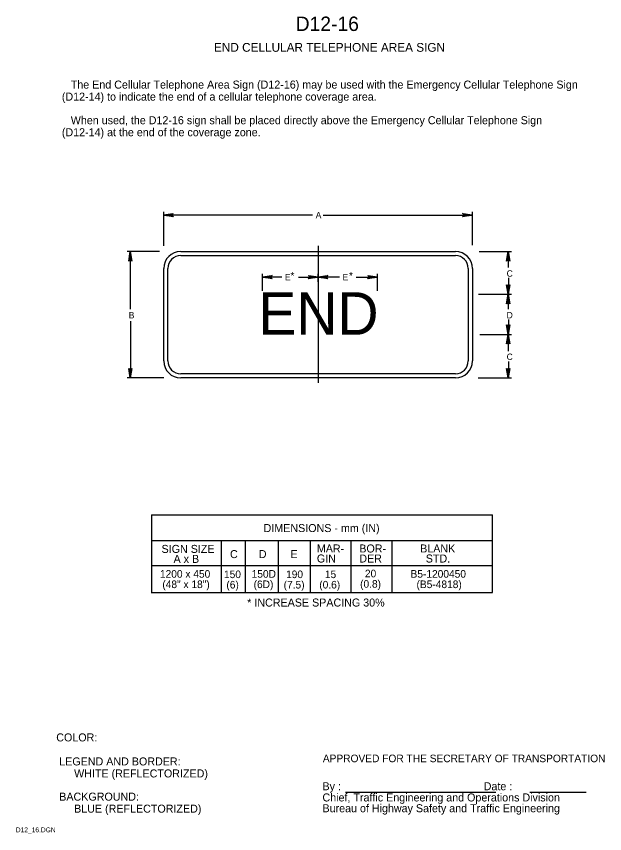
# Model space of a CAD drawing. Extents: x 0.013 to 0.196, y 0.004 to 0.259.
import ezdxf

# ---------------------------------------------------------------- set-up
doc = ezdxf.new("R2010")
doc.units = 0
for name, color, linetype in [('Level 1', 7, 'Continuous'), ('Level 2', 7, 'Continuous'), ('Level 3', 7, 'Continuous')]:
    doc.layers.add(name, color=color, linetype=linetype)

# ---------------------------------------------------------------- blocks, each defined once
blk = doc.blocks.new('RARROW')
at = {"layer": 'Level 3'}
for p, q in [((-2.156, 0.285), (-2.2665, 0.384625)), ((-2.2665, 0.384625), (0, 0)), ((0, 0), (-2.2665, -0.379125)), ((-2.156, 0.285), (-2.075625, 0.12075)), ((0, 0), (-2.156, 0.285)), ((-2.14975, -0.2705), (0, 0)), ((-2.075625, 0.12075), (0, 0)), ((0, 0), (-2.074, -0.108)), ((-2.2665, -0.379125), (-2.14975, -0.2705)), ((-2.074, -0.108), (-2.14975, -0.2705))]:
    blk.add_line(p, q, dxfattribs=at)

msp = doc.modelspace()

# ---------------------------------------------------------------- linework, layer by layer
at = {"layer": 'Level 1'}
for p, q in [((0.10687, 0.1875), (0.10687, 0.14475)), ((0.11544, 0.01695), (0.16242, 0.01695)), ((0.17295, 0.01695), (0.19056, 0.01695))]:
    msp.add_line(p, q, dxfattribs=at)
at = {"layer": 'Level 3'}
for p, q in [((0.05868, 0.18751), (0.05868, 0.19813)), ((0.10518, 0.19713), (0.05868, 0.19713)), ((0.10843, 0.19713), (0.15506, 0.19713)), ((0.15506, 0.18776), (0.15506, 0.19813)), ((0.05731, 0.18576), (0.04731, 0.18576)), ((0.04831, 0.16776), (0.04831, 0.18576)), ((0.06398, 0.18576), (0.14976, 0.18576)), ((0.06398, 0.18446), (0.14976, 0.18446)), ((0.15718, 0.18576), (0.16731, 0.18576)), ((0.16631, 0.18076), (0.16631, 0.18576)), ((0.05868, 0.15156), (0.05868, 0.18046)), ((0.05998, 0.15156), (0.05998, 0.18046)), ((0.08956, 0.17345), (0.08956, 0.17876)), ((0.10693, 0.17626), (0.10693, 0.17876)), ((0.12543, 0.17345), (0.12543, 0.17876)), ((0.15376, 0.18046), (0.15376, 0.15156)), ((0.15506, 0.18046), (0.15506, 0.15156)), ((0.09556, 0.17776), (0.08956, 0.17776)), ((0.10081, 0.17776), (0.10693, 0.17776)), ((0.11356, 0.17776), (0.10693, 0.17776)), ((0.11881, 0.17776), (0.12543, 0.17776)), ((0.16631, 0.17751), (0.16631, 0.17238)), ((0.15693, 0.17238), (0.16731, 0.17238)), ((0.16631, 0.16776), (0.16631, 0.17238)), ((0.04831, 0.16401), (0.04831, 0.14626)), ((0.16631, 0.16451), (0.16631, 0.15988)), ((0.15743, 0.15988), (0.16731, 0.15988)), ((0.16631, 0.15463), (0.16631, 0.15988)), ((0.16631, 0.15138), (0.16631, 0.14626)), ((0.05868, 0.14626), (0.04731, 0.14626)), ((0.14976, 0.14756), (0.06398, 0.14756)), ((0.14976, 0.14626), (0.06398, 0.14626)), ((0.15681, 0.14626), (0.16731, 0.14626)), ((0.05489, 0.10349), (0.05489, 0.07926)), ((0.05491, 0.10351), (0.16133, 0.10351)), ((0.16125, 0.1035), (0.16125, 0.07925)), ((0.16133, 0.09539), (0.055, 0.09539)), ((0.07664, 0.09524), (0.07664, 0.07926)), ((0.08414, 0.09549), (0.08414, 0.07926)), ((0.09439, 0.09524), (0.09439, 0.07926)), ((0.10439, 0.09524), (0.10439, 0.07926)), ((0.11714, 0.09524), (0.11714, 0.07926)), ((0.12989, 0.09524), (0.12989, 0.07926)), ((0.05471, 0.08764), (0.16133, 0.08764)), ((0.05471, 0.07926), (0.16133, 0.07926))]:
    msp.add_line(p, q, dxfattribs=at)
for centre, radius, start, end in [((0.06398, 0.18046), 0.0053, 90, 180), ((0.06398, 0.18046), 0.004, 90, 180), ((0.14976, 0.18046), 0.0053, 0, 90), ((0.14976, 0.18046), 0.004, 0, 90), ((0.06398, 0.15156), 0.0053, 180, 270), ((0.06398, 0.15156), 0.004, 180, 270), ((0.14976, 0.15156), 0.0053, 270, 0), ((0.14976, 0.15156), 0.004, 270, 0)]:
    msp.add_arc(centre, radius, start, end, dxfattribs=at)

# ---------------------------------------------------------------- block references
at = {"layer": 'Level 3', "xscale": 0.0013236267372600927, "yscale": 0.001309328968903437}
for p, rotation in [((0.05863, 0.19712), 180), ((0.04825, 0.18575), 90), ((0.16625, 0.18575), 90), ((0.0895, 0.17775), 180), ((0.10687, 0.17775), 180), ((0.16625, 0.17238), -90), ((0.16625, 0.17238), 90), ((0.16625, 0.15988), -90), ((0.16625, 0.15988), 90), ((0.04825, 0.14625), -90), ((0.16625, 0.14625), -90)]:
    msp.add_blockref('RARROW', p, dxfattribs=dict(at, rotation=rotation))
for p in [(0.155, 0.19712), (0.10687, 0.17775), (0.12538, 0.17775)]:
    msp.add_blockref('RARROW', p, dxfattribs=at)

# ---------------------------------------------------------------- texts
at = {"layer": 'Level 1'}
for s, height, p in [('D12-16', 0.0045, (0.09988, 0.25462)), ('END CELLULAR TELEPHONE AREA SIGN', 0.0027503, (0.07437, 0.24813)), ('COLOR:', 0.0025, (0.02513, 0.03275)), ('APPROVED FOR THE SECRETARY OF TRANSPORTATION', 0.0023752, (0.10837, 0.02625)), (' LEGEND AND BORDER:', 0.0024998, (0.02513, 0.02525)), ('      WHITE (REFLECTORIZED)', 0.0024998, (0.02513, 0.0215)), ('By :                                                Date :', 0.0024998, (0.10825, 0.0175)), (' BACKGROUND:', 0.0024998, (0.02513, 0.01425)), ('Chief, Traffic Engineering and Operations Division', 0.0024998, (0.10825, 0.014)), ('      BLUE (REFLECTORIZED)', 0.0024998, (0.02513, 0.0105)), ('Bureau of Highway Safety and Traffic Engineering', 0.0024998, (0.10825, 0.01063)), ('D12_16.DGN', 0.0015, (0.0125, 0.00438))]:
    msp.add_text(s, height=height, dxfattribs=at).set_placement(p)
at = {"layer": 'Level 2'}
for s, height, p in [('   The End Cellular Telephone Area Sign (D12-16) may be used with the Emergency Cellular Telephone Sign', 0.00249975, (0.02687, 0.23663)), ('(D12-14) to indicate the end of a cellular telephone coverage area.', 0.0024998, (0.02687, 0.23287)), ('   When used, the D12-16 sign shall be placed directly above the Emergency Cellular Telephone Sign', 0.0024998, (0.02687, 0.2255)), ('(D12-14) at the end of the coverage zone.', 0.0024998, (0.02687, 0.22175))]:
    msp.add_text(s, height=height, dxfattribs=at).set_placement(p)
at = {"layer": 'Level 3'}
for s, height, p in [('A', 0.002, (0.10612, 0.19612)), ('E ', 0.002, (0.0965, 0.17675)), ('*', 0.00238, (0.09825, 0.177)), ('E ', 0.002, (0.1145, 0.17675)), ('*', 0.00238, (0.1165, 0.177)), ('C', 0.002, (0.16575, 0.17788)), ('END', 0.013289, (0.08825, 0.15975)), ('B', 0.002, (0.04775, 0.16487)), ('D', 0.002, (0.16575, 0.16487)), ('C', 0.002, (0.16575, 0.15188)), ('DIMENSIONS - mm (IN)', 0.0024998, (0.08987, 0.09813)), ('SIGN SIZE', 0.0025, (0.058, 0.09162)), ('C', 0.0025, (0.07938, 0.09)), ('D', 0.0025, (0.08837, 0.09)), ('E', 0.0025, (0.09825, 0.09)), ('MAR-', 0.0025, (0.1065, 0.09175)), ('BOR-', 0.0025, (0.11975, 0.09175)), ('BLANK', 0.0025, (0.13875, 0.09175)), ('A x B', 0.0025, (0.06175, 0.0885)), ('GIN', 0.0025, (0.1065, 0.08862)), ('DER', 0.0025, (0.11975, 0.08862)), ('STD.', 0.0025, (0.1405, 0.08862)), ('1200 x 450', 0.002375, (0.0575, 0.08388)), ('150', 0.002375, (0.0775, 0.08375)), ('150D', 0.002375, (0.08613, 0.08388)), ('190', 0.002375, (0.09688, 0.08375)), ('15', 0.002375, (0.109, 0.08375)), ('20', 0.002375, (0.1215, 0.084)), ('B5-1200450', 0.002375, (0.13575, 0.08388)), ('(48" x 18")', 0.0023752, (0.05825, 0.08063)), ('(6)', 0.002375, (0.07825, 0.0805)), ('(6D)', 0.002375, (0.08675, 0.08063)), ('(7.5)', 0.002375, (0.09613, 0.0805)), ('(0.6)', 0.002375, (0.10725, 0.0805)), ('(0.8)', 0.002375, (0.12, 0.08075)), ('(B5-4818)', 0.002375, (0.13762, 0.08063)), ('* INCREASE SPACING 30%', 0.0024998, (0.08475, 0.07487))]:
    msp.add_text(s, height=height, dxfattribs=at).set_placement(p)

doc.saveas('drawing.dxf')
